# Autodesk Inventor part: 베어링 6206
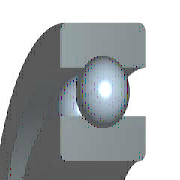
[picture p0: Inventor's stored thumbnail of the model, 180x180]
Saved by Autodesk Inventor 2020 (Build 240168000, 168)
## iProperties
Created: 2009-02
Part Number: 베어링 6206
Material: 강철, 연강
Document SubType Name: Modeling
Standard: KS B 2023
Designer: mdu
Standards Organization: KS
Language: ko-KR
Size Designation: 6206 - 30 x 62 x 16
Categories: <MemberInstance><Categories><Category DisplayName="샤프트 부품" InternalName="7f7aeb1f-a693-4053-b835-cee3144e0d98" Mnemonic="SHFT"><Category DisplayName="베어링" Inter
Density: 1 g/cm^3
Appearance: 노란색
IsCustomPart: 0
Author: mdu
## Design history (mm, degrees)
sketch "스케치" dims "d0" = 8.32 (= -0.26 x WD + 0.26 x BD)
  geometry: L1 (3.84, 23)-(12.16, 23); L2 (8, 23)-(8, 18.84); L3 (8, 23)-(8, 27.16); L4 (4.909, 20.216)-(0, 20.216); L5 (0, 15)-(16, 15); L6 (4.909, 25.784)-(0, 25.784); L7 (0, 31)-(16, 31); L8 (16, 15)-(16, 20.216); L9 (11.091, 20.216)-(16, 20.216); L10 (11.091, 25.784)-(16, 25.784); L11 (16, 31)-(16, 25.784); L12 (-1.4, 0)-(8.4, 0) reference; L13 (0, -0.3)-(0, 5.3) reference
  constraints: 22 end point, 4 point on line, 2 collinear, 2 perpendicular, 2 symmetric about line, 1 midpoint, 1 parallel, 14 other
  dimensions: "d9" = 30 diameter of L5 L12 (= WD); "d11" = 62 diameter of L7 L12 (= BD); "d12" = 16 distance between parallel lines of L8 L13 (= KB); "d13" = 40.432 diameter of L9 L12 (= 0.326 x BD + 0.674 x WD)
revolve "본체" stored, may be unused: angle "d6" = 90 deg
revolve "볼" stored, may be unused: angle "d7" = 90 deg
pattern_circular "IDS_ARRAYBALL[SIMPL:T]" dims angle "d3" = 360 deg
body "Solid1"
fillet "모깎기1" dims "d1" = 1 (= KRS)
other parameters: "WD" = 30 [user parameter; used in 5 equation terms], "BD" = 62 [user parameter; used in 5 equation terms], "KB" = 16 [user parameter; used in 1 equation term], "KRS" = 1 [user parameter; used in 1 equation term], "d4" = 0, "d5" = 0, "d8" = 0, "d14" = 0, "d15" = 0, "BBA" = 0 [user parameter], "BC0" = 1.12e+07 [user parameter], "BC" = 1.95e+07 [user parameter], "BR" = 31 (= 0.5 x BD) [user parameter], "WR" = 15 (= 0.5 x WD) [user parameter]
